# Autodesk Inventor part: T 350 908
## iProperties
Company: Mayer & Müller AG Schaltgeräte
Created: 2006-01
Part Number: T 350 908
Material: 2.0060.30
Document SubType Name: Sheet Metal
Designer: I.Baliuc
Manufacturer: Standard
Standards Organization: Custom
Description: Kupferband
Density: 8.94 g/cm^3
Sheet Metal Rule: Standard
HalbzeugNorm: DIN 1751
Zweck: für Spule
Abmessung: 2,5x30-628
Author: T.Messerschmitt
Revision Number: 350908
Keywords: 382212
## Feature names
1. Extrusion1
2. Bohrung1 [Hole]
3. Bohrung2 [Hole]
4. ExtrusionAbwicklung2
